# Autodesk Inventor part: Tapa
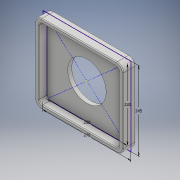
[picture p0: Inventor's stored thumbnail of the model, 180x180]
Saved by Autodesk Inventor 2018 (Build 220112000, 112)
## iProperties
Created: 2022-01
Part Number: Tapa
Material: Generic
Document SubType Name: Modeling
Designer: Asus
Density: 1 g/cm^3
Appearance: Default
Author: Asus
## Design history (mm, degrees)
sketch "Boceto1"
  geometry: L1 (125, 110)-(-125, 110); L2 (-125, 110)-(-125, -110); L3 (-125, -110)-(125, -110); L4 (125, -110)-(125, 110); L5 (125, 110)-(-125, -110); L6 (-125, 110)-(125, -110); L7 (137.5, 122.5)-(-137.5, 122.5); L8 (-137.5, 122.5)-(-137.5, -122.5); L9 (-137.5, -122.5)-(137.5, -122.5); L10 (137.5, -122.5)-(137.5, 122.5); L11 (137.5, 122.5)-(-137.5, -122.5); L12 (-137.5, 122.5)-(137.5, -122.5); 1 further point
  constraints: 24 end point, 4 midpoint, 4 parallel, 2 horizontal, 2 perpendicular
  dimensions: "d0" = 250 distance of L3.end L2.end; "d1" = 220 distance of L2.end L1.end; "d2" = 275 distance of L9.end L8.end; "d3" = 245 distance of L8.end L7.end
extrude "Extrusión1" new body sketch "Boceto1" distance "d4" = 25; taper "d5" = 0 deg
extrude "Extrusión2" join sketch "Boceto1" distance "d6" = 15; taper "d7" = 0 deg
sketch "Boceto2"
  geometry: C1 r 60 at (0, 0); 1 further point
  constraints: 1 centre point, 1 coincident
  dimensions: "d8" = 120 diameter of C1
fillet "Empalme1" dims "d9" = 20
fillet "Empalme2" dims "d10" = 10
extrude "Extrusión3" cut sketch "Boceto2" distance "d11" = 25; taper "d12" = 0 deg
fillet "Empalme3" dims "d13" = 2.5
node "Sólido1"
